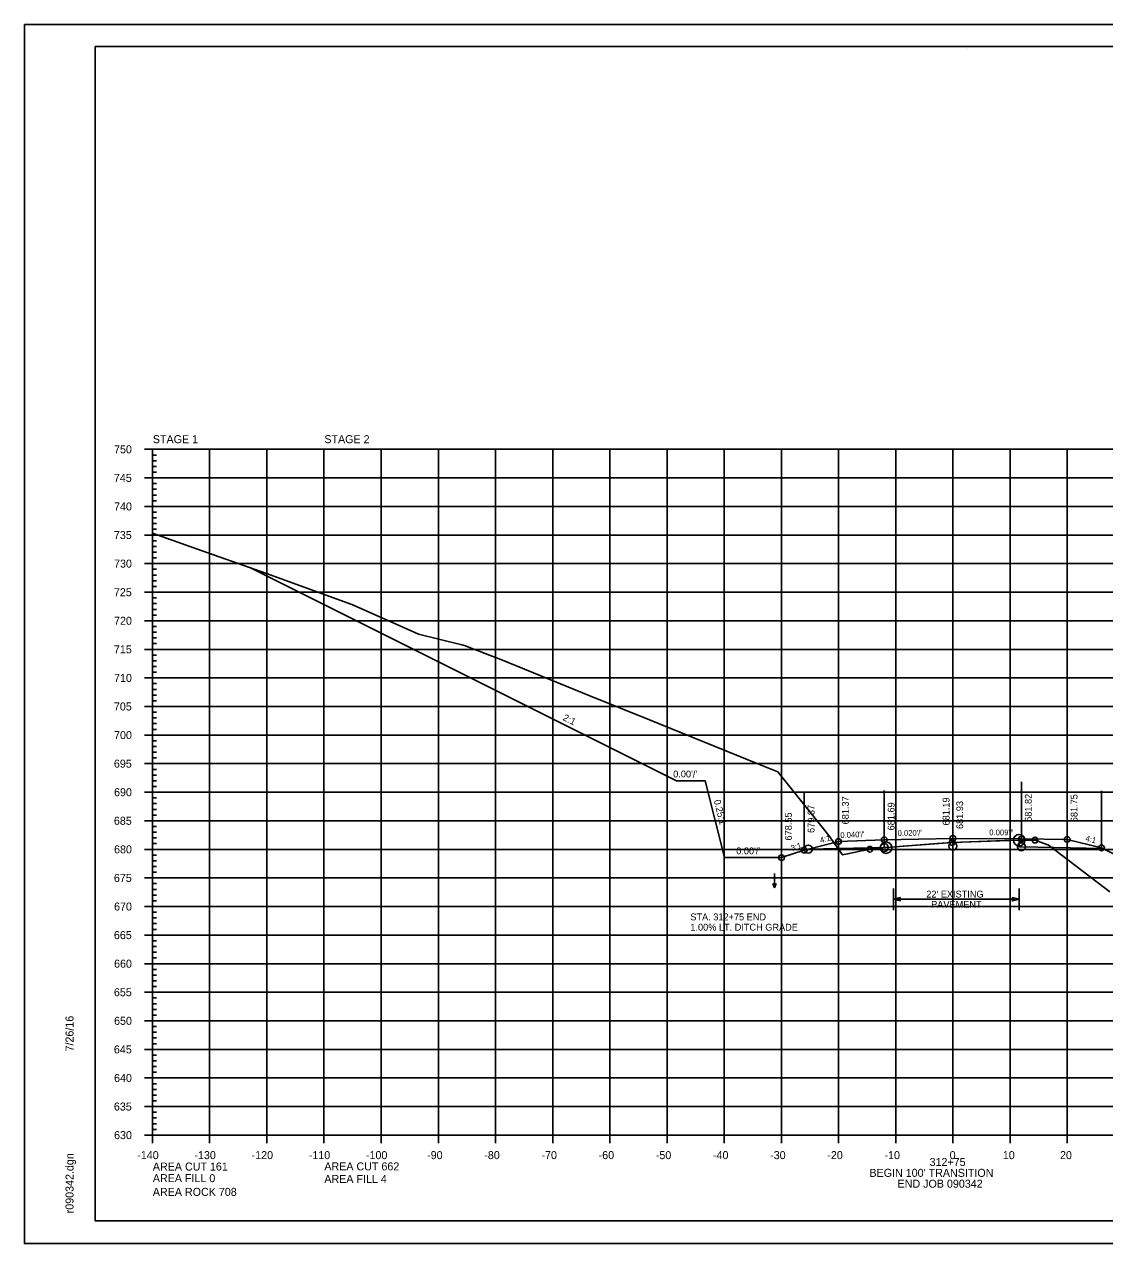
# Model space of a CAD drawing. Extents: x 1370515 to 1370849, y 383299 to 386073.
# Drawn here: x 1370515.4 to 1370704.3, y 385432.8 to 385646.1 of the extents above; entities that cross this region are included whole.
import ezdxf

# ---------------------------------------------------------------- set-up
doc = ezdxf.new("R2010")
doc.units = 0
for name, color, linetype in [('R_Alt Surface', 7, 'Continuous'), ('R_Axis', 7, 'Continuous'), ('R_Axis Annot', 7, 'Continuous'), ('R_Border', 7, 'Continuous'), ('R_Detour', 7, 'Continuous'), ('R_Drive', 7, 'Continuous'), ('R_Exist Surface', 7, 'Continuous'), ('R_Fin Surface', 7, 'Continuous'), ('R_Grid', 7, 'Continuous'), ('R_No Plot', 7, 'Continuous'), ('R_ROW Annot', 7, 'Continuous'), ('R_Water Annot', 7, 'Continuous'), ('R_Xsect Elev', 7, 'Continuous'), ('R_Xsect Slope', 7, 'Continuous')]:
    doc.layers.add(name, color=color, linetype=linetype)

msp = doc.modelspace()

# ---------------------------------------------------------------- linework, layer by layer
at = {"layer": 'R_Alt Surface'}
msp.add_lwpolyline([(1370652.52, 385501.84), (1370665.8, 385502.11), (1370666.12, 385502.11), (1370666.12, 385502.09), (1370677.68, 385502.98), (1370689.39, 385503.4), (1370689.39, 385502.24), (1370689.8, 385502.24), (1370703.97, 385501.95)], dxfattribs=at)
at = {"layer": 'R_Axis'}
for p, q in [((1370536.4, 385571.79), (1370539.2, 385571.79)), ((1370537.8, 385451.79), (1370537.8, 385571.79)), ((1370537.8, 385570.79), (1370538.5, 385570.79)), ((1370537.8, 385569.79), (1370538.5, 385569.79)), ((1370537.8, 385568.79), (1370538.5, 385568.79)), ((1370537.8, 385567.79), (1370538.5, 385567.79)), ((1370536.4, 385566.79), (1370539.2, 385566.79)), ((1370537.8, 385565.79), (1370538.5, 385565.79)), ((1370537.8, 385564.79), (1370538.5, 385564.79)), ((1370537.8, 385563.79), (1370538.5, 385563.79)), ((1370536.4, 385561.79), (1370539.2, 385561.79)), ((1370537.8, 385562.79), (1370538.5, 385562.79)), ((1370537.8, 385560.79), (1370538.5, 385560.79)), ((1370537.8, 385559.79), (1370538.5, 385559.79)), ((1370537.8, 385558.79), (1370538.5, 385558.79)), ((1370536.4, 385556.79), (1370539.2, 385556.79)), ((1370537.8, 385557.79), (1370538.5, 385557.79)), ((1370537.8, 385555.79), (1370538.5, 385555.79)), ((1370537.8, 385554.79), (1370538.5, 385554.79)), ((1370537.8, 385553.79), (1370538.5, 385553.79)), ((1370537.8, 385552.79), (1370538.5, 385552.79)), ((1370536.4, 385551.79), (1370539.2, 385551.79)), ((1370537.8, 385550.79), (1370538.5, 385550.79)), ((1370537.8, 385549.79), (1370538.5, 385549.79)), ((1370537.8, 385548.79), (1370538.5, 385548.79)), ((1370536.4, 385546.79), (1370539.2, 385546.79)), ((1370537.8, 385547.79), (1370538.5, 385547.79)), ((1370537.8, 385545.79), (1370538.5, 385545.79)), ((1370537.8, 385544.79), (1370538.5, 385544.79)), ((1370537.8, 385543.79), (1370538.5, 385543.79)), ((1370536.4, 385541.79), (1370539.2, 385541.79)), ((1370537.8, 385542.79), (1370538.5, 385542.79)), ((1370537.8, 385540.79), (1370538.5, 385540.79)), ((1370537.8, 385539.79), (1370538.5, 385539.79)), ((1370537.8, 385538.79), (1370538.5, 385538.79)), ((1370537.8, 385537.79), (1370538.5, 385537.79)), ((1370536.4, 385536.79), (1370539.2, 385536.79)), ((1370537.8, 385535.79), (1370538.5, 385535.79)), ((1370537.8, 385534.79), (1370538.5, 385534.79)), ((1370537.8, 385533.79), (1370538.5, 385533.79)), ((1370536.4, 385531.79), (1370539.2, 385531.79)), ((1370537.8, 385532.79), (1370538.5, 385532.79)), ((1370537.8, 385530.79), (1370538.5, 385530.79)), ((1370537.8, 385529.79), (1370538.5, 385529.79)), ((1370537.8, 385528.79), (1370538.5, 385528.79)), ((1370536.4, 385526.79), (1370539.2, 385526.79)), ((1370537.8, 385527.79), (1370538.5, 385527.79)), ((1370537.8, 385525.79), (1370538.5, 385525.79)), ((1370537.8, 385524.79), (1370538.5, 385524.79)), ((1370537.8, 385523.79), (1370538.5, 385523.79)), ((1370537.8, 385522.79), (1370538.5, 385522.79)), ((1370536.4, 385521.79), (1370539.2, 385521.79)), ((1370537.8, 385520.79), (1370538.5, 385520.79)), ((1370537.8, 385519.79), (1370538.5, 385519.79)), ((1370537.8, 385518.79), (1370538.5, 385518.79)), ((1370536.4, 385516.79), (1370539.2, 385516.79)), ((1370537.8, 385517.79), (1370538.5, 385517.79)), ((1370537.8, 385515.79), (1370538.5, 385515.79)), ((1370537.8, 385514.79), (1370538.5, 385514.79)), ((1370536.4, 385511.79), (1370539.2, 385511.79)), ((1370537.8, 385513.79), (1370538.5, 385513.79)), ((1370537.8, 385512.79), (1370538.5, 385512.79)), ((1370537.8, 385510.79), (1370538.5, 385510.79)), ((1370537.8, 385509.79), (1370538.5, 385509.79)), ((1370537.8, 385508.79), (1370538.5, 385508.79)), ((1370537.8, 385507.79), (1370538.5, 385507.79)), ((1370536.4, 385506.79), (1370539.2, 385506.79)), ((1370537.8, 385505.79), (1370538.5, 385505.79)), ((1370537.8, 385504.79), (1370538.5, 385504.79)), ((1370537.8, 385503.79), (1370538.5, 385503.79)), ((1370536.4, 385501.79), (1370539.2, 385501.79)), ((1370537.8, 385502.79), (1370538.5, 385502.79)), ((1370537.8, 385500.79), (1370538.5, 385500.79)), ((1370537.8, 385499.79), (1370538.5, 385499.79)), ((1370536.4, 385496.79), (1370539.2, 385496.79)), ((1370537.8, 385498.79), (1370538.5, 385498.79)), ((1370537.8, 385497.79), (1370538.5, 385497.79)), ((1370537.8, 385495.79), (1370538.5, 385495.79)), ((1370537.8, 385494.79), (1370538.5, 385494.79)), ((1370537.8, 385493.79), (1370538.5, 385493.79)), ((1370537.8, 385492.79), (1370538.5, 385492.79)), ((1370536.4, 385491.79), (1370539.2, 385491.79)), ((1370537.8, 385490.79), (1370538.5, 385490.79)), ((1370537.8, 385489.79), (1370538.5, 385489.79)), ((1370537.8, 385488.79), (1370538.5, 385488.79)), ((1370536.4, 385486.79), (1370539.2, 385486.79)), ((1370537.8, 385487.79), (1370538.5, 385487.79)), ((1370537.8, 385485.79), (1370538.5, 385485.79)), ((1370537.8, 385484.79), (1370538.5, 385484.79)), ((1370537.8, 385483.79), (1370538.5, 385483.79)), ((1370537.8, 385482.79), (1370538.5, 385482.79)), ((1370536.4, 385481.79), (1370539.2, 385481.79)), ((1370537.8, 385480.79), (1370538.5, 385480.79)), ((1370537.8, 385479.79), (1370538.5, 385479.79)), ((1370537.8, 385478.79), (1370538.5, 385478.79)), ((1370537.8, 385477.79), (1370538.5, 385477.79)), ((1370536.4, 385476.79), (1370539.2, 385476.79)), ((1370537.8, 385475.79), (1370538.5, 385475.79)), ((1370537.8, 385474.79), (1370538.5, 385474.79)), ((1370537.8, 385473.79), (1370538.5, 385473.79)), ((1370536.4, 385471.79), (1370539.2, 385471.79)), ((1370537.8, 385472.79), (1370538.5, 385472.79)), ((1370537.8, 385470.79), (1370538.5, 385470.79)), ((1370537.8, 385469.79), (1370538.5, 385469.79)), ((1370537.8, 385468.79), (1370538.5, 385468.79)), ((1370537.8, 385467.79), (1370538.5, 385467.79)), ((1370536.4, 385466.79), (1370539.2, 385466.79)), ((1370537.8, 385465.79), (1370538.5, 385465.79)), ((1370537.8, 385464.79), (1370538.5, 385464.79)), ((1370537.8, 385463.79), (1370538.5, 385463.79)), ((1370537.8, 385462.79), (1370538.5, 385462.79)), ((1370536.4, 385461.79), (1370539.2, 385461.79)), ((1370537.8, 385460.79), (1370538.5, 385460.79)), ((1370537.8, 385459.79), (1370538.5, 385459.79)), ((1370537.8, 385458.79), (1370538.5, 385458.79)), ((1370536.4, 385456.79), (1370539.2, 385456.79)), ((1370537.8, 385457.79), (1370538.5, 385457.79)), ((1370537.8, 385455.79), (1370538.5, 385455.79)), ((1370537.8, 385454.79), (1370538.5, 385454.79)), ((1370537.8, 385453.79), (1370538.5, 385453.79)), ((1370537.8, 385450.39), (1370537.8, 385453.19)), ((1370537.8, 385452.79), (1370538.5, 385452.79)), ((1370547.8, 385450.39), (1370547.8, 385453.19)), ((1370557.8, 385450.39), (1370557.8, 385453.19)), ((1370567.8, 385450.39), (1370567.8, 385453.19)), ((1370577.8, 385450.39), (1370577.8, 385453.19)), ((1370587.8, 385450.39), (1370587.8, 385453.19)), ((1370597.8, 385450.39), (1370597.8, 385453.19)), ((1370607.8, 385450.39), (1370607.8, 385453.19)), ((1370617.8, 385450.39), (1370617.8, 385453.19)), ((1370627.8, 385450.39), (1370627.8, 385453.19)), ((1370637.8, 385450.39), (1370637.8, 385453.19)), ((1370647.8, 385450.39), (1370647.8, 385453.19)), ((1370657.8, 385450.39), (1370657.8, 385453.19)), ((1370667.8, 385450.39), (1370667.8, 385453.19)), ((1370677.8, 385450.39), (1370677.8, 385453.19)), ((1370687.8, 385450.39), (1370687.8, 385453.19)), ((1370697.8, 385450.39), (1370697.8, 385453.19)), ((1370536.4, 385451.79), (1370539.2, 385451.79)), ((1370537.8, 385451.79), (1370817.8, 385451.79))]:
    msp.add_line(p, q, dxfattribs=at)
at = {"layer": 'R_Border'}
for p, q in [((1370527.8, 385642.25), (1370843.98, 385642.25)), ((1370527.8, 385436.79), (1370527.8, 385642.25)), ((1370680.32, 385641.99), (1370680.32, 385641.99)), ((1370680.32, 385641.99), (1370680.32, 385641.99)), ((1370527.8, 385436.79), (1370527.8, 385436.79)), ((1370843.98, 385436.79), (1370527.8, 385436.79))]:
    msp.add_line(p, q, dxfattribs=at)
at = {"layer": 'R_Exist Surface'}
msp.add_lwpolyline([(1370537.8, 385557.11), (1370544.51, 385554.73), (1370557.75, 385550.08), (1370572.64, 385544.66), (1370583.03, 385540.03), (1370584.32, 385539.44), (1370591.93, 385537.55), (1370592.54, 385537.39), (1370593.25, 385537.11), (1370598.72, 385535.01), (1370614.3, 385528.63), (1370624.73, 385524.45), (1370643.67, 385516.74), (1370647.21, 385515.33), (1370656.09, 385504.22), (1370658.48, 385500.82), (1370659.35, 385501), (1370661.28, 385501.42), (1370662.01, 385501.57), (1370662.23, 385501.62), (1370662.51, 385501.67), (1370663.3, 385501.82), (1370663.92, 385501.87), (1370666.12, 385502.09), (1370675.07, 385502.8), (1370677.68, 385502.98), (1370686.84, 385503.32), (1370689.39, 385503.4), (1370691.57, 385503.42), (1370692.17, 385503.42), (1370694.26, 385502.67), (1370694.46, 385502.6), (1370695.72, 385501.64), (1370705.26, 385494.38)], dxfattribs=at)
at = {"layer": 'R_Fin Surface'}
msp.add_lwpolyline([(1370554.83, 385551.11), (1370629.47, 385513.79), (1370634.47, 385513.79), (1370637.83, 385500.34), (1370647.83, 385500.34), (1370651.8, 385501.66), (1370652.52, 385501.84), (1370657.8, 385503.16), (1370665.8, 385503.48), (1370677.8, 385503.72), (1370689.8, 385503.61), (1370697.8, 385503.54), (1370703.8, 385502.04), (1370774.8, 385466.54), (1370804.8, 385466.54), (1370821.08, 385471.96)], dxfattribs=at)
at = {"layer": 'R_Grid'}
for p, q in [((1370537.8, 385571.79), (1370817.8, 385571.79)), ((1370537.8, 385451.79), (1370537.8, 385571.79)), ((1370547.8, 385451.79), (1370547.8, 385571.79)), ((1370557.8, 385451.79), (1370557.8, 385571.79)), ((1370567.8, 385451.79), (1370567.8, 385571.79)), ((1370577.8, 385451.79), (1370577.8, 385571.79)), ((1370587.8, 385451.79), (1370587.8, 385571.79)), ((1370597.8, 385451.79), (1370597.8, 385571.79)), ((1370607.8, 385451.79), (1370607.8, 385571.79)), ((1370617.8, 385451.79), (1370617.8, 385571.79)), ((1370627.8, 385451.79), (1370627.8, 385571.79)), ((1370637.8, 385451.79), (1370637.8, 385571.79)), ((1370647.8, 385451.79), (1370647.8, 385571.79)), ((1370657.8, 385451.79), (1370657.8, 385571.79)), ((1370667.8, 385451.79), (1370667.8, 385571.79)), ((1370677.8, 385451.79), (1370677.8, 385571.79)), ((1370687.8, 385451.79), (1370687.8, 385571.79)), ((1370697.8, 385451.79), (1370697.8, 385571.79)), ((1370537.8, 385566.79), (1370817.8, 385566.79)), ((1370537.8, 385561.79), (1370817.8, 385561.79)), ((1370537.8, 385556.79), (1370817.8, 385556.79)), ((1370537.8, 385551.79), (1370817.8, 385551.79)), ((1370537.8, 385546.79), (1370817.8, 385546.79)), ((1370537.8, 385541.79), (1370817.8, 385541.79)), ((1370537.8, 385536.79), (1370817.8, 385536.79)), ((1370537.8, 385531.79), (1370817.8, 385531.79)), ((1370537.8, 385526.79), (1370817.8, 385526.79)), ((1370537.8, 385521.79), (1370817.8, 385521.79)), ((1370537.8, 385516.79), (1370817.8, 385516.79)), ((1370537.8, 385511.79), (1370817.8, 385511.79)), ((1370537.8, 385506.79), (1370817.8, 385506.79)), ((1370537.8, 385501.79), (1370817.8, 385501.79)), ((1370537.8, 385496.79), (1370817.8, 385496.79)), ((1370537.8, 385491.79), (1370817.8, 385491.79)), ((1370537.8, 385486.79), (1370817.8, 385486.79)), ((1370537.8, 385481.79), (1370817.8, 385481.79)), ((1370537.8, 385476.79), (1370817.8, 385476.79)), ((1370537.8, 385471.79), (1370817.8, 385471.79)), ((1370537.8, 385466.79), (1370817.8, 385466.79)), ((1370537.8, 385461.79), (1370817.8, 385461.79)), ((1370537.8, 385456.79), (1370817.8, 385456.79)), ((1370537.8, 385451.79), (1370817.8, 385451.79))]:
    msp.add_line(p, q, dxfattribs=at)
at = {"layer": 'R_No Plot'}
for p, q in [((1370515.4, 385646.14), (1370848.73, 385646.14)), ((1370515.4, 385432.81), (1370848.73, 385432.81))]:
    msp.add_line(p, q, dxfattribs=at)
for points in [[(1370515.39, 385646.14), (1370848.73, 385646.14), (1370848.73, 385432.81), (1370515.39, 385432.81)], [(1370761.72, 385642.25), (1370761.72, 385632.37), (1370797.45, 385632.37), (1370797.45, 385629.45), (1370820.65, 385629.45), (1370820.65, 385606.23), (1370843.98, 385606.23), (1370843.98, 385436.79), (1370527.8, 385436.79), (1370527.8, 385642.25)]]:
    msp.add_lwpolyline(points, close=True, dxfattribs=at)
for centre, radius in [((1370657.8, 385503.16), 0.5), ((1370665.8, 385503.48), 0.5), ((1370677.68, 385502.98), 0.5), ((1370677.8, 385503.72), 0.5), ((1370689.39, 385503.4), 1), ((1370689.8, 385503.61), 0.5), ((1370692.17, 385503.42), 0.5), ((1370697.8, 385503.54), 0.5), ((1370651.8, 385501.66), 0.5), ((1370651.8, 385501.66), 0.5), ((1370652.52, 385501.84), 0.7), ((1370663.3, 385501.82), 0.5), ((1370665.8, 385502.11), 0.7), ((1370666.12, 385502.09), 1), ((1370677.8, 385502.35), 0.7), ((1370677.8, 385502.35), 0.7), ((1370689.8, 385502.24), 0.7), ((1370703.8, 385502.04), 0.5), ((1370703.8, 385502.04), 0.5), ((1370647.83, 385500.34), 0.5)]:
    msp.add_circle(centre, radius, dxfattribs=at)
at = {"layer": 'R_ROW Annot'}
for p, q in [((1370667.41, 385491.18), (1370667.41, 385494.94)), ((1370689.41, 385491.18), (1370689.41, 385494.94)), ((1370689.41, 385493.06), (1370667.41, 385493.06))]:
    msp.add_line(p, q, dxfattribs=at)
for points in [[(1370668.61, 385492.76), (1370667.41, 385493.06), (1370668.61, 385493.36)], [(1370688.21, 385493.36), (1370689.41, 385493.06), (1370688.21, 385492.76)]]:
    msp.add_lwpolyline(points, close=True, dxfattribs=at)
at = {"layer": 'R_Water Annot'}
for p, q in [((1370646.6, 385497.57), (1370646.6, 385495.06)), ((1370646.6, 385495.06), (1370646.32, 385495.83)), ((1370646.6, 385495.06), (1370646.88, 385495.83))]:
    msp.add_line(p, q, dxfattribs=at)
at = {"layer": 'R_Xsect Elev'}
for p, q in [((1370657.8, 385503.16), (1370657.8, 385513.16)), ((1370665.8, 385502.11), (1370665.8, 385512.11)), ((1370677.8, 385502.35), (1370677.8, 385512.35)), ((1370677.82, 385502.97), (1370677.82, 385512.97)), ((1370689.8, 385503.61), (1370689.8, 385513.61)), ((1370697.8, 385503.54), (1370697.8, 385513.54)), ((1370703.8, 385502.04), (1370703.8, 385512.04)), ((1370647.83, 385500.34), (1370647.83, 385510.34)), ((1370651.8, 385501.66), (1370651.8, 385511.66))]:
    msp.add_line(p, q, dxfattribs=at)

# ---------------------------------------------------------------- texts
at = {"layer": 'R_Axis'}
msp.add_text('-', height=0.0001, dxfattribs=at).set_placement((1370537.8, 385451.79))
at = {"layer": 'R_Axis Annot'}
for s, p in [('STAGE 1', (1370537.86, 385572.86)), ('STAGE 2', (1370567.86, 385572.86)), ('750', (1370531.08, 385571.09)), ('745', (1370531.05, 385566.09)), ('740', (1370531.08, 385561.09)), ('735', (1370531.05, 385556.09)), ('730', (1370531.08, 385551.09)), ('725', (1370531.05, 385546.09)), ('720', (1370531.08, 385541.09)), ('715', (1370531.05, 385536.09)), ('710', (1370531.08, 385531.09)), ('705', (1370531.05, 385526.09)), ('700', (1370531.08, 385521.09)), ('695', (1370531.05, 385516.09)), ('690', (1370531.08, 385511.09)), ('685', (1370531.05, 385506.09)), ('680', (1370531.08, 385501.09)), ('675', (1370531.05, 385496.09)), ('670', (1370531.08, 385491.09)), ('665', (1370531.05, 385486.09)), ('660', (1370531.08, 385481.09)), ('655', (1370531.05, 385476.09)), ('650', (1370531.08, 385471.09)), ('645', (1370531.05, 385466.09)), ('640', (1370531.08, 385461.09)), ('635', (1370531.05, 385456.09)), ('630', (1370531.08, 385451.09)), ('-140', (1370535.14, 385447.59)), ('-130', (1370545.14, 385447.59)), ('-120', (1370555.14, 385447.59)), ('-110', (1370565.14, 385447.59)), ('-100', (1370575.14, 385447.59)), ('-90', (1370585.84, 385447.59)), ('-80', (1370595.84, 385447.59)), ('-70', (1370605.84, 385447.59)), ('-60', (1370615.84, 385447.59)), ('-50', (1370625.84, 385447.59)), ('-40', (1370635.84, 385447.59)), ('-30', (1370645.84, 385447.59)), ('-20', (1370655.84, 385447.59)), ('-10', (1370665.84, 385447.59)), ('312+75', (1370673.73, 385446.39)), ('0', (1370677.24, 385447.59)), ('10', (1370686.54, 385447.59)), ('20', (1370696.54, 385447.59)), ('AREA CUT 161', (1370537.86, 385445.59)), ('AREA CUT 662', (1370567.86, 385445.62)), ("BEGIN 100' TRANSITION", (1370663.21, 385444.49)), ('AREA FILL 0', (1370537.86, 385443.56)), ('AREA FILL 4', (1370567.86, 385443.42)), ('END JOB 090342', (1370668.13, 385442.59)), ('AREA ROCK 708', (1370537.86, 385441.16))]:
    msp.add_text(s, height=1.4, dxfattribs=at).set_placement(p)
at = {"layer": 'R_Border'}
for s, p in [('7/26/16', (1370523.99, 385466.43)), ('r090342.dgn', (1370523.99, 385438.11))]:
    msp.add_text(s, height=1.4, rotation=90, dxfattribs=at).set_placement(p)
at = {"layer": 'R_Detour'}
msp.add_text('2:1', height=1.2, rotation=333.4349, dxfattribs=at).set_placement((1370609.47, 385524.46))
at = {"layer": 'R_Drive'}
for s, p in [('STA. 312+75 END', (1370631.88, 385489.37)), ('1.00% LT. DITCH GRADE', (1370631.88, 385487.57))]:
    msp.add_text(s, height=1.2, dxfattribs=at).set_placement(p)
at = {"layer": 'R_Fin Surface'}
for p in [(1370628.88, 385514.38), (1370639.91, 385500.93)]:
    msp.add_text("0.00'/'", height=1.2, dxfattribs=at).set_placement(p)
msp.add_text('0.25:1', height=1.2, rotation=284.0362, dxfattribs=at).set_placement((1370635.97, 385510.33))
at = {"layer": 'R_No Plot'}
for p in [(1370544.47, 385554.68), (1370572.6, 385544.61), (1370584.27, 385539.39), (1370592.5, 385537.34), (1370598.68, 385534.96), (1370624.69, 385524.4), (1370647.17, 385515.28), (1370661.24, 385501.37), (1370662.19, 385501.57), (1370694.42, 385502.55), (1370658.44, 385500.77)]:
    msp.add_text('+', height=0.1, dxfattribs=at).set_placement(p)
at = {"layer": 'R_ROW Annot'}
for s, p in [("22' EXISTING", (1370673.15, 385493.36)), ('PAVEMENT', (1370674, 385491.56))]:
    msp.add_text(s, height=1.2, dxfattribs=at).set_placement(p)
at = {"layer": 'R_Xsect Elev'}
for s, p in [('681.37', (1370659.6, 385506.16)), ('681.69', (1370667.6, 385505.11)), ('681.19', (1370677.22, 385505.97)), ('681.93', (1370679.6, 385505.35)), ('681.82', (1370691.6, 385506.61)), ('681.75', (1370699.6, 385506.54)), ('678.55', (1370649.63, 385503.34)), ('679.87', (1370653.6, 385504.66))]:
    msp.add_text(s, height=1.2, rotation=90, dxfattribs=at).set_placement(p)
at = {"layer": 'R_Xsect Slope'}
for s, rotation, p in [('4:1', 14.0362, (1370654.68, 385502.9)), ("0.040'/'", 2.2906, (1370658.13, 385503.78)), ("0.020'/'", 1.1458, (1370668.14, 385504.13)), ("0.009'/'", 359.4758, (1370684.16, 385504.27)), ('4:1', 345.9638, (1370700.92, 385503.28)), ('3:1', 18.4349, (1370649.66, 385501.48))]:
    msp.add_text(s, height=1, rotation=rotation, dxfattribs=at).set_placement(p)

doc.saveas('drawing.dxf')
